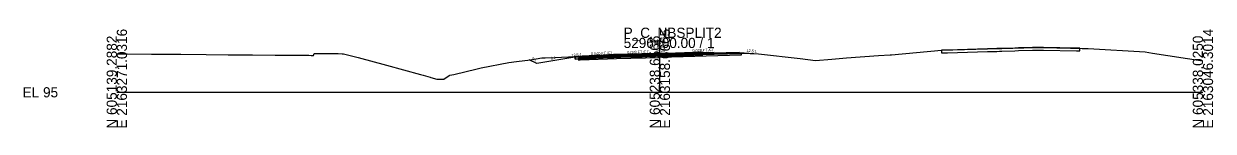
# Model space of a CAD drawing. Extents: x -26 to 1303, y -10 to 12038.
# Drawn here: x -25.7 to 302.8, y 8490.3 to 8517.8 of the extents above; entities that cross this region are included whole.
import ezdxf

# ---------------------------------------------------------------- set-up
doc = ezdxf.new("R2010")
doc.units = 0
for name, color, linetype in [('RD_GPK_XS_Cell', 7, 'Continuous'), ('RD_XS_Base', 7, 'Continuous'), ('RD_XS_ExGround', 7, 'Continuous'), ('RD_XS_ExPaveRet', 7, 'Continuous'), ('RD_XS_Greenside', 7, 'Continuous'), ('RD_XS_Pave', 7, 'Continuous'), ('RD_XS_PaveOvlay_CP', 7, 'Continuous'), ('RD_XS_TieSlope', 7, 'Continuous'), ('RD_XS_TX_Elev_EX', 7, 'Continuous'), ('RD_XS_TX_Elev_PR', 7, 'Continuous'), ('RD_XS_TX_ShdSlope', 7, 'Continuous'), ('RD_XS_TX_Slope', 7, 'Continuous')]:
    doc.layers.add(name, color=color, linetype=linetype)

msp = doc.modelspace()

# ---------------------------------------------------------------- linework, layer by layer
at = {"layer": 'RD_GPK_XS_Cell'}
for p, q in [((150, 8500), (150, 8515)), ((0, 8500), (150, 8500)), ((150, 8500), (300, 8500))]:
    msp.add_line(p, q, dxfattribs=at)
at = {"layer": 'RD_XS_Base'}
for p, q in [((128, 8509.4), (127.5, 8509.38)), ((127.5, 8509.38), (127.5, 8509.38)), ((127.5, 8509.38), (127.5, 8508.88)), ((138, 8509.8), (128, 8509.4)), ((128, 8509.4), (128, 8509.4)), ((128, 8508.9), (138, 8509.3)), ((150, 8510.11), (138, 8509.8)), ((138, 8509.8), (138, 8509.8)), ((138, 8509.3), (150, 8509.61)), ((138, 8509.3), (138, 8509.3)), ((150, 8510.11), (172.5, 8510.7)), ((150, 8509.61), (150, 8510.27)), ((150, 8510.27), (150, 8510.27)), ((150, 8510.27), (150, 8510.27)), ((150, 8510.27), (150, 8510.11)), ((172.5, 8510.2), (150, 8509.61)), ((150, 8510.11), (150, 8510.11)), ((150, 8509.61), (150, 8510.11)), ((150, 8510.11), (150, 8510.11)), ((150, 8510.11), (150, 8510.11)), ((150, 8509.61), (150, 8509.61)), ((172, 8510.68), (172, 8510.68)), ((172, 8510.68), (172, 8510.68)), ((172, 8510.68), (172, 8510.68)), ((172, 8510.18), (172, 8510.18)), ((172, 8510.18), (172, 8510.18)), ((172.5, 8510.7), (172.5, 8510.2)), ((172.5, 8510.66), (172.5, 8510.66)), ((127.5, 8508.88), (128, 8508.9)), ((128, 8508.9), (128, 8508.9))]:
    msp.add_line(p, q, dxfattribs=at)
at = {"layer": 'RD_XS_ExGround'}
msp.add_lwpolyline([(0, 8510.6), (2.82, 8510.56), (9.57, 8510.52), (17.49, 8510.5), (17.55, 8510.5), (17.65, 8510.5), (24.64, 8510.41), (30.75, 8510.34), (31.41, 8510.33), (37.48, 8510.29), (43.73, 8510.25), (53.08, 8510.2), (53.64, 8510.18), (54.33, 8510.15), (54.4, 8510.39), (54.48, 8510.65), (54.68, 8510.65), (54.83, 8510.65), (58.34, 8510.65), (61.15, 8510.67), (62.26, 8510.62), (62.66, 8510.63), (66.7, 8509.54), (74.51, 8507.5), (83.88, 8504.89), (84.64, 8504.68), (86.58, 8504.15), (86.76, 8504.07), (88.42, 8503.57), (88.56, 8503.57), (90.37, 8503.57), (91.83, 8504.61), (91.94, 8504.68), (93.07, 8504.94), (99.56, 8506.5), (100.63, 8506.76), (108.28, 8508.18), (110.43, 8508.5), (114.25, 8508.98), (117.42, 8509.5), (118.36, 8509.49), (120.95, 8509.63), (126.58, 8509.88), (134.37, 8510.27), (137.28, 8510.38), (141.2, 8510.48), (143.57, 8510.52), (144.15, 8510.54), (144.76, 8510.54), (145.08, 8510.55), (146.43, 8510.64), (151.65, 8510.75), (151.79, 8510.73), (154.3, 8510.82), (161.85, 8511.04), (164.86, 8511), (172.56, 8510.74), (177.28, 8510.57), (188.77, 8509.29), (192.96, 8508.8), (197.52, 8509.17), (201.59, 8509.5), (210.39, 8510.12), (213.6, 8510.36), (213.94, 8510.36), (220.86, 8510.92), (227.78, 8511.58), (240.46, 8511.97), (243.03, 8512.03), (244.47, 8512.08), (250.52, 8512.26), (253.19, 8512.35), (253.94, 8512.37), (255.75, 8512.36), (263.46, 8512.19), (264.67, 8512.18), (265.96, 8512.14), (266.62, 8512.1), (268.31, 8512.02), (284, 8511.17), (286.05, 8510.82), (300, 8508.66)], dxfattribs=at)
at = {"layer": 'RD_XS_ExPaveRet'}
for points in [[(255.94, 8512.36), (255.83, 8512.36), (255.38, 8512.36), (253.94, 8512.37), (252.89, 8512.34), (249.07, 8512.22), (248.02, 8512.19), (244.47, 8512.08), (243.85, 8512.06), (243.03, 8512.03), (241.61, 8512), (240.46, 8511.97), (229.42, 8511.63), (227.78, 8511.58), (227.78, 8511.58), (227.78, 8510.98), (227.78, 8510.83), (227.78, 8510.83), (229.42, 8510.88), (240.46, 8511.22), (241.61, 8511.25), (243.03, 8511.28), (243.85, 8511.31), (244.47, 8511.33), (248.02, 8511.44), (249.07, 8511.47), (252.89, 8511.59), (253.94, 8511.62), (255.38, 8511.61), (255.83, 8511.61), (255.94, 8511.61), (265.07, 8511.42), (265.96, 8511.39), (265.96, 8511.48), (265.96, 8512.14), (265.07, 8512.17), (255.94, 8512.36)], [(255.94, 8512.36), (255.83, 8512.36), (255.38, 8512.36), (253.94, 8512.37), (252.89, 8512.34), (249.07, 8512.22), (248.02, 8512.19), (244.47, 8512.08), (243.85, 8512.06), (243.03, 8512.03), (241.61, 8512), (240.46, 8511.97), (229.42, 8511.63), (227.78, 8511.58), (227.78, 8510.98), (227.78, 8510.83), (229.42, 8510.88), (240.46, 8511.22), (241.61, 8511.25), (243.03, 8511.28), (243.85, 8511.31), (244.47, 8511.33), (248.02, 8511.44), (249.07, 8511.47), (252.89, 8511.59), (253.94, 8511.62), (255.38, 8511.61), (255.83, 8511.61), (255.94, 8511.61), (265.07, 8511.42), (265.96, 8511.39), (265.96, 8511.48), (265.96, 8512.14), (265.07, 8512.17), (255.94, 8512.36)], [(161.85, 8511.04), (161.85, 8511.04), (161.85, 8510.29), (161.85, 8510.29), (161.85, 8510.29), (154.3, 8510.07), (154.3, 8510.07), (151.79, 8509.98), (151.65, 8510), (151.65, 8510), (146.43, 8509.89), (146.43, 8509.89), (145.08, 8509.8), (145.08, 8509.8), (144.76, 8509.79), (144.76, 8509.79), (144.76, 8509.79), (144.76, 8509.79), (144.15, 8509.79), (143.57, 8509.77), (143.57, 8509.77), (141.2, 8509.73), (141.2, 8509.73), (137.28, 8509.63), (137.28, 8509.63), (134.37, 8509.52), (134.37, 8509.52), (126.58, 8509.13), (126.58, 8509.13), (126.58, 8509.13), (126.58, 8509.88), (126.58, 8509.88), (126.58, 8509.88), (126.58, 8509.88), (134.37, 8510.27), (134.37, 8510.27), (137.28, 8510.38), (137.28, 8510.38), (141.2, 8510.48), (141.2, 8510.48), (143.57, 8510.52), (143.57, 8510.52), (144.15, 8510.54), (144.76, 8510.54), (144.76, 8510.54), (144.76, 8510.54), (144.76, 8510.54), (145.08, 8510.55), (145.08, 8510.55), (146.43, 8510.64), (146.43, 8510.64), (151.65, 8510.75), (151.65, 8510.75), (151.79, 8510.73), (154.3, 8510.82), (154.3, 8510.82), (161.85, 8511.04), (161.85, 8511.04), (161.85, 8511.04)], [(161.85, 8511.04), (154.3, 8510.82), (151.79, 8510.73), (151.65, 8510.75), (146.43, 8510.64), (145.08, 8510.55), (144.76, 8510.54), (144.15, 8510.54), (143.57, 8510.52), (141.2, 8510.48), (137.28, 8510.38), (134.37, 8510.27), (126.58, 8509.88), (126.58, 8509.13), (134.37, 8509.52), (137.28, 8509.63), (141.2, 8509.73), (143.57, 8509.77), (144.15, 8509.79), (144.76, 8509.79), (145.08, 8509.8), (146.43, 8509.89), (151.65, 8510), (151.79, 8509.98), (154.3, 8510.07), (161.85, 8510.29), (161.85, 8510.29), (161.85, 8511.04), (161.85, 8511.04)]]:
    msp.add_lwpolyline(points, dxfattribs=at)
at = {"layer": 'RD_XS_Greenside'}
for p, q in [((126, 8509.56), (116, 8507.89)), ((116, 8507.89), (113.9, 8508.94))]:
    msp.add_line(p, q, dxfattribs=at)
at = {"layer": 'RD_XS_Pave'}
for p, q in [((138, 8510.12), (128, 8509.72)), ((128, 8509.56), (138, 8509.96)), ((138, 8509.96), (128, 8509.56)), ((128, 8509.4), (138, 8509.8)), ((128, 8509.72), (128, 8509.72)), ((128, 8509.72), (128, 8509.56)), ((128, 8509.56), (128, 8509.56)), ((128, 8509.56), (128, 8509.4)), ((150, 8510.43), (138, 8510.12)), ((138, 8509.96), (150, 8510.27)), ((150, 8510.27), (138, 8509.96)), ((138, 8510.12), (138, 8510.12)), ((138, 8509.8), (150, 8510.11)), ((138, 8509.96), (138, 8509.96)), ((138, 8509.96), (138, 8509.96)), ((138, 8509.8), (138, 8509.8)), ((172, 8511), (150, 8510.43)), ((172, 8510.84), (150, 8510.27)), ((150, 8510.27), (172, 8510.84)), ((150, 8510.11), (172, 8510.68)), ((150, 8510.43), (150, 8510.43)), ((150, 8510.27), (150, 8510.27)), ((150, 8510.27), (150, 8510.27)), ((150, 8510.27), (150, 8510.11)), ((150, 8510.27), (150, 8510.27)), ((150, 8510.11), (150, 8510.27)), ((150, 8510.27), (150, 8510.27)), ((150, 8510.27), (150, 8510.27)), ((150, 8510.11), (150, 8510.11)), ((150, 8510.11), (150, 8510.11)), ((172, 8510.84), (172, 8511)), ((172, 8511), (172, 8511)), ((172, 8511), (172, 8511)), ((172, 8511), (172, 8511)), ((172, 8510.68), (172, 8510.84)), ((172, 8510.84), (172, 8510.84)), ((172, 8510.84), (172, 8510.84)), ((172, 8510.84), (172, 8510.84)), ((172, 8510.84), (172, 8510.84)), ((172, 8510.84), (172, 8510.84)), ((172, 8510.68), (172, 8510.68)), ((172, 8510.68), (172, 8510.68))]:
    msp.add_line(p, q, dxfattribs=at)
at = {"layer": 'RD_XS_PaveOvlay_CP'}
for p, q in [((138, 8510.12), (128, 8509.72)), ((150, 8510.43), (138, 8510.12)), ((138, 8510.12), (138, 8510.12)), ((172, 8511), (150, 8510.43)), ((150, 8510.43), (150, 8510.43)), ((172, 8511), (172, 8511)), ((172, 8511), (172, 8511))]:
    msp.add_line(p, q, dxfattribs=at)
at = {"layer": 'RD_XS_TieSlope'}
for p, q in [((128, 8509.72), (126, 8509.56)), ((172, 8511), (177.28, 8510.57))]:
    msp.add_line(p, q, dxfattribs=at)

# ---------------------------------------------------------------- texts
at = {"layer": 'RD_GPK_XS_Cell'}
for s, p in [('E 2163271.0316', (2.8, 8490)), ('E 2163158.6665', (152.8, 8490)), ('E 2163046.3014', (302.8, 8490)), ('N 605139.2882', (0, 8490)), ('N 605238.6566', (150, 8490)), ('N 605338.0250', (300, 8490))]:
    msp.add_text(s, height=2.8, rotation=90, dxfattribs=at).set_placement(p)
for s, p in [('P_C_NBSPLIT2', (140, 8515)), ('5296+00.00 / 1', (140, 8512.2)), ('EL 95', (-26, 8498.6))]:
    msp.add_text(s, height=2.8, dxfattribs=at).set_placement(p)
at = {"layer": 'RD_XS_TX_Elev_EX'}
msp.add_text('105.71', height=0.6, rotation=90, dxfattribs=at).set_placement((149.68, 8511.24))
at = {"layer": 'RD_XS_TX_Elev_PR'}
msp.add_text('105.43', height=1, rotation=90, dxfattribs=at).set_placement((151.34, 8510.95))
at = {"layer": 'RD_XS_TX_ShdSlope'}
for rotation, p in [(4.5739, (125.58, 8509.82)), (355.4261, (173.89, 8511.15))]:
    msp.add_text('12.5:1', height=0.75, rotation=rotation, dxfattribs=at).set_placement(p)
at = {"layer": 'RD_XS_TX_Slope'}
for s, rotation, p in [('2:1', 333.4349, (114.5, 8509.11)), ('6:1', 9.4642, (119.89, 8508.97)), ('0.040 FT./FT.', 2.2906, (130.99, 8510.25)), ('0.028 FT./FT.', 1.6039, (141, 8510.61)), ('0.028 FT./FT.', 1.6039, (159, 8511.12))]:
    msp.add_text(s, height=0.75, rotation=rotation, dxfattribs=at).set_placement(p)

doc.saveas('drawing.dxf')
